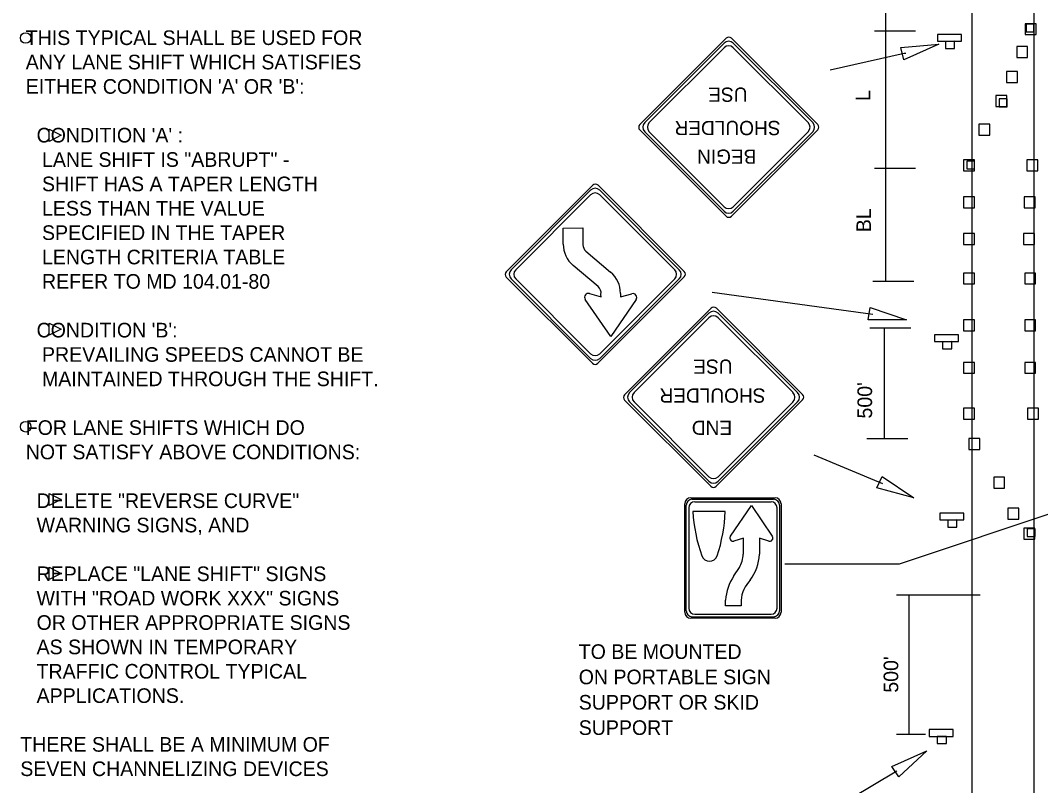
# Model space of a CAD drawing. Extents: x 1531.38 to 1538.58, y 1529.59 to 1539.28.
# Drawn here: x 1531.395 to 1535.582, y 1533.489 to 1536.629 of the extents above; entities that cross this region are included whole.
import ezdxf

# ---------------------------------------------------------------- set-up
doc = ezdxf.new("R2010")
doc.units = 0
for name, color, linetype in [('DETL-DIMS', 7, 'Continuous'), ('DETL-LINE', 7, 'Continuous'), ('DETL-NOTE', 7, 'Continuous'), ('USER-BORD', 7, 'Continuous')]:
    doc.layers.add(name, color=color, linetype=linetype)

# ---------------------------------------------------------------- blocks, each defined once
blk = doc.blocks.new('CD20')
at = {"layer": 'USER-BORD'}
blk.add_lwpolyline([(-0.0625, -0.0625), (0, -0.0625), (0, 0), (-0.0625, 0)], close=True, dxfattribs=at)
blk = doc.blocks.new('SIGN13')
at = {"layer": 'USER-BORD'}
for points in [[(-0.0134, 0.0182), (0.011, 0.0189), (0.011, 0.0371), (-0.0134, 0.0371)], [(-0.0314, 0.0182), (-0.0314, 0), (0.032, 0), (0.032, 0.0182)]]:
    blk.add_lwpolyline(points, close=True, dxfattribs=at)

msp = doc.modelspace()

# ---------------------------------------------------------------- linework, layer by layer
at = {"layer": 'DETL-DIMS'}
for p, q in [((1534.9463, 1538.5537), (1534.9463, 1535.5589)), ((1534.901, 1536.5864), (1535.0689, 1536.5864)), ((1535.0219, 1536.4925), (1534.719, 1536.4242)), ((1535.0299, 1536.4925), (1535.0219, 1536.4925)), ((1534.901, 1536.0219), (1535.0689, 1536.0219)), ((1534.8937, 1535.5589), (1535.0617, 1535.5589)), ((1534.8937, 1535.4219), (1534.2339, 1535.512)), ((1534.8818, 1535.3674), (1535.0497, 1535.3674)), ((1534.9408, 1535.3674), (1534.9408, 1534.9127)), ((1534.8698, 1534.9127), (1535.0377, 1534.9127)), ((1534.9353, 1534.7269), (1534.6525, 1534.8449)), ((1535.6998, 1534.63), (1535.0012, 1534.3974)), ((1535.0012, 1534.3974), (1534.5326, 1534.3973)), ((1535.3342, 1534.2704), (1534.9914, 1534.2702)), ((1535.0412, 1534.2702), (1535.0412, 1533.6978)), ((1535.1099, 1533.6978), (1534.9914, 1533.6978)), ((1534.9925, 1533.5485), (1534.8025, 1533.4337))]:
    msp.add_line(p, q, dxfattribs=at)
for points in [[(1535.0215, 1536.4671), (1535.0084, 1536.517), (1535.1649, 1536.5316)], [(1534.8743, 1535.3994), (1534.8827, 1535.4504), (1535.0315, 1535.3996)], [(1534.9107, 1534.7101), (1534.9319, 1534.7572), (1535.0627, 1534.6701)], [(1535.0002, 1533.5243), (1534.9719, 1533.5676), (1535.1158, 1533.6309)]]:
    msp.add_lwpolyline(points, close=True, dxfattribs=at)
at = {"layer": 'DETL-LINE'}
for p, q in [((1535.3002, 1538.9346), (1535.3002, 1531.7918)), ((1535.5552, 1538.9346), (1535.5552, 1531.7918)), ((1534.2919, 1536.5559), (1533.9372, 1536.2011)), ((1534.6678, 1536.2019), (1534.3139, 1536.5559)), ((1533.9572, 1536.2094), (1534.2833, 1536.5356)), ((1534.2833, 1536.5168), (1533.976, 1536.2094)), ((1534.321, 1536.5356), (1534.6471, 1536.2094)), ((1534.6283, 1536.2094), (1534.321, 1536.5168)), ((1531.5127, 1536.1322), (1531.5127, 1536.1822)), ((1531.5127, 1536.1822), (1531.5627, 1536.1572)), ((1533.9372, 1536.1792), (1534.2912, 1535.8253)), ((1534.2833, 1535.8456), (1533.9572, 1536.1718)), ((1533.976, 1536.1718), (1534.2833, 1535.8644)), ((1534.3131, 1535.8253), (1534.6678, 1536.1799)), ((1534.6471, 1536.1718), (1534.321, 1535.8456)), ((1534.321, 1535.8644), (1534.6283, 1536.1718)), ((1534.6283, 1536.2094), (1534.6283, 1536.2094)), ((1531.5627, 1536.1572), (1531.5127, 1536.1322)), ((1533.744, 1535.9522), (1533.3893, 1535.5975)), ((1533.4092, 1535.6058), (1533.7354, 1535.932)), ((1534.1199, 1535.5983), (1533.7659, 1535.9522)), ((1533.7731, 1535.932), (1534.0992, 1535.6058)), ((1533.7354, 1535.9132), (1533.4281, 1535.6058)), ((1534.0804, 1535.6058), (1533.773, 1535.9132)), ((1533.623, 1535.7767), (1533.7036, 1535.7769)), ((1533.6231, 1535.7105), (1533.623, 1535.7767)), ((1533.7036, 1535.7769), (1533.7037, 1535.7082)), ((1533.7158, 1535.6821), (1533.8176, 1535.5959)), ((1533.766, 1535.5367), (1533.6636, 1535.6234)), ((1534.0804, 1535.6058), (1534.0804, 1535.6058)), ((1533.3893, 1535.5755), (1533.7433, 1535.2216)), ((1533.7354, 1535.242), (1533.4092, 1535.5681)), ((1533.4281, 1535.5682), (1533.7354, 1535.2608)), ((1533.7652, 1535.2216), (1534.1199, 1535.5763)), ((1534.0992, 1535.5681), (1533.7731, 1535.242)), ((1533.7731, 1535.2608), (1534.0804, 1535.5681)), ((1533.7311, 1535.5081), (1533.778, 1535.4939)), ((1533.7781, 1535.4939), (1533.7776, 1535.5042)), ((1533.7776, 1535.5042), (1533.7776, 1535.5042)), ((1533.8581, 1535.5087), (1533.8581, 1535.4943)), ((1533.8581, 1535.4943), (1533.9046, 1535.5073)), ((1533.8189, 1535.3317), (1533.7135, 1535.4841)), ((1533.9219, 1535.4833), (1533.8189, 1535.3317)), ((1534.2297, 1535.4477), (1533.8749, 1535.0929)), ((1533.8949, 1535.1012), (1534.221, 1535.4274)), ((1534.6055, 1535.0937), (1534.2516, 1535.4477)), ((1534.2587, 1535.4274), (1534.5849, 1535.1012)), ((1531.5127, 1535.337), (1531.5127, 1535.387)), ((1531.5127, 1535.387), (1531.5627, 1535.362)), ((1534.221, 1535.4086), (1533.9137, 1535.1012)), ((1534.5661, 1535.1012), (1534.2587, 1535.4086)), ((1531.5627, 1535.362), (1531.5127, 1535.337)), ((1534.5661, 1535.1012), (1534.5661, 1535.1012)), ((1533.8749, 1535.071), (1534.2289, 1534.7171)), ((1534.221, 1534.7374), (1533.8949, 1535.0636)), ((1533.9137, 1535.0636), (1534.221, 1534.7562)), ((1534.2509, 1534.7171), (1534.6055, 1535.0717)), ((1534.5849, 1535.0636), (1534.2587, 1534.7374)), ((1534.2587, 1534.7562), (1534.5661, 1535.0636)), ((1531.5127, 1534.6377), (1531.5127, 1534.6877)), ((1531.5127, 1534.6877), (1531.5627, 1534.6627)), ((1531.5627, 1534.6627), (1531.5127, 1534.6377)), ((1534.1463, 1534.67), (1534.4924, 1534.67)), ((1534.1524, 1534.6639), (1534.4861, 1534.6639)), ((1534.1216, 1534.2003), (1534.1216, 1534.6453)), ((1534.1277, 1534.2064), (1534.1277, 1534.6391)), ((1534.1381, 1534.6288), (1534.1381, 1534.2168)), ((1534.1628, 1534.6535), (1534.4759, 1534.6535)), ((1534.3091, 1534.5116), (1534.3952, 1534.638)), ((1534.3952, 1534.638), (1534.4812, 1534.5116)), ((1534.5006, 1534.2168), (1534.5006, 1534.6288)), ((1534.5109, 1534.6391), (1534.5109, 1534.2064)), ((1534.5171, 1534.6453), (1534.5171, 1534.2003)), ((1534.1554, 1534.6143), (1534.2872, 1534.6143)), ((1534.3622, 1534.5045), (1534.3238, 1534.492)), ((1534.3622, 1534.4384), (1534.3622, 1534.5043)), ((1534.4663, 1534.492), (1534.4279, 1534.5045)), ((1534.4281, 1534.5043), (1534.4281, 1534.4384)), ((1531.5127, 1534.3345), (1531.5127, 1534.3845)), ((1531.5127, 1534.3845), (1531.5627, 1534.3595)), ((1534.3238, 1534.3491), (1534.3461, 1534.3837)), ((1531.5627, 1534.3595), (1531.5127, 1534.3345)), ((1534.2893, 1534.2268), (1534.2893, 1534.2492)), ((1534.3527, 1534.2492), (1534.3527, 1534.2268)), ((1534.3527, 1534.2268), (1534.2893, 1534.2268)), ((1534.4924, 1534.1756), (1534.1463, 1534.1756)), ((1534.1524, 1534.1817), (1534.4861, 1534.1817)), ((1534.1628, 1534.1921), (1534.4759, 1534.1921))]:
    msp.add_line(p, q, dxfattribs=at)
for points in [[(1535.5191, 1536.5705), (1535.5639, 1536.5705), (1535.5639, 1536.6153), (1535.5191, 1536.6153)], [(1535.4842, 1536.4767), (1535.529, 1536.4767), (1535.529, 1536.5215), (1535.4842, 1536.5215)], [(1535.4427, 1536.3742), (1535.4875, 1536.3742), (1535.4875, 1536.419), (1535.4427, 1536.419)], [(1535.3991, 1536.2761), (1535.4439, 1536.2761), (1535.4439, 1536.3209), (1535.3991, 1536.3209)], [(1535.3293, 1536.1583), (1535.3741, 1536.1583), (1535.3741, 1536.2031), (1535.3293, 1536.2031)], [(1535.2661, 1536.0121), (1535.3109, 1536.0121), (1535.3109, 1536.0569), (1535.2661, 1536.0569)], [(1535.5256, 1536.0121), (1535.5704, 1536.0121), (1535.5704, 1536.0569), (1535.5256, 1536.0569)], [(1535.2661, 1535.8595), (1535.3109, 1535.8595), (1535.3109, 1535.9043), (1535.2661, 1535.9043)], [(1535.5149, 1535.8595), (1535.5597, 1535.8595), (1535.5597, 1535.9043), (1535.5149, 1535.9043)], [(1535.2661, 1535.7092), (1535.3109, 1535.7092), (1535.3109, 1535.754), (1535.2661, 1535.754)], [(1535.5126, 1535.7092), (1535.5574, 1535.7092), (1535.5574, 1535.754), (1535.5126, 1535.754)], [(1535.2661, 1535.5471), (1535.3109, 1535.5471), (1535.3109, 1535.5919), (1535.2661, 1535.5919)], [(1535.5173, 1535.5471), (1535.5621, 1535.5471), (1535.5621, 1535.5919), (1535.5173, 1535.5919)], [(1535.2661, 1535.3546), (1535.3109, 1535.3546), (1535.3109, 1535.3994), (1535.2661, 1535.3994)], [(1535.5173, 1535.3546), (1535.5621, 1535.3546), (1535.5621, 1535.3994), (1535.5173, 1535.3994)], [(1535.2661, 1535.1808), (1535.3109, 1535.1808), (1535.3109, 1535.2256), (1535.2661, 1535.2256)], [(1535.5173, 1535.1808), (1535.5621, 1535.1808), (1535.5621, 1535.2256), (1535.5173, 1535.2256)], [(1535.2661, 1534.9929), (1535.3109, 1534.9929), (1535.3109, 1535.0377), (1535.2661, 1535.0377)], [(1535.529, 1534.9929), (1535.5738, 1534.9929), (1535.5738, 1535.0377), (1535.529, 1535.0377)], [(1535.2881, 1534.8678), (1535.3329, 1534.8678), (1535.3329, 1534.9126), (1535.2881, 1534.9126)], [(1535.3898, 1534.7097), (1535.4346, 1534.7097), (1535.4346, 1534.7545), (1535.3898, 1534.7545)], [(1535.4484, 1534.5819), (1535.4932, 1534.5819), (1535.4932, 1534.6267), (1535.4484, 1534.6267)], [(1535.5141, 1534.4997), (1535.5589, 1534.4997), (1535.5589, 1534.5445), (1535.5141, 1534.5445)]]:
    msp.add_lwpolyline(points, close=True, dxfattribs=at)
for centre in [(1531.4164, 1536.5567), (1531.4164, 1534.9614)]:
    msp.add_circle(centre, 0.0217, dxfattribs=at)
for centre, radius, start, end in [((1534.3029, 1536.5449), 0.0155, 45, 135), ((1534.3022, 1536.5168), 0.0266, 45, 135), ((1534.3021, 1536.498), 0.0266, 45, 135), ((1533.9482, 1536.1901), 0.0155, 135, 225), ((1533.976, 1536.1906), 0.0266, 135, 225), ((1533.9948, 1536.1906), 0.0266, 135, 225), ((1534.6095, 1536.1906), 0.0266, 315, 45), ((1534.6284, 1536.1906), 0.0266, 315, 45), ((1534.6569, 1536.1909), 0.0155, 315, 45), ((1533.7542, 1535.9131), 0.0266, 45, 135), ((1533.7542, 1535.8943), 0.0266, 45, 135), ((1533.755, 1535.9412), 0.0155, 45, 135), ((1534.3022, 1535.8832), 0.0266, 225, 315), ((1534.3022, 1535.8644), 0.0266, 225, 315), ((1534.3021, 1535.8362), 0.0155, 225, 315), ((1533.7375, 1535.7107), 0.1144, 180.094, 229.7591), ((1533.738, 1535.7082), 0.0343, 180.094, 229.7591), ((1533.4003, 1535.5865), 0.0155, 135, 225), ((1533.428, 1535.587), 0.0266, 135, 225), ((1533.4468, 1535.587), 0.0266, 135, 225), ((1533.7436, 1535.5085), 0.1144, 0.094, 49.7591), ((1534.0616, 1535.5869), 0.0266, 315, 45), ((1534.0804, 1535.5869), 0.0266, 315, 45), ((1534.1089, 1535.5873), 0.0155, 315, 45), ((1533.7265, 1535.4929), 0.0157, 73.1964, 214.3543), ((1533.7438, 1535.5105), 0.0343, 349.3489, 49.7591), ((1533.9088, 1535.4921), 0.0157, 325.8336, 105.5836), ((1534.2398, 1535.3898), 0.0266, 45, 135), ((1534.2399, 1535.4086), 0.0266, 45, 135), ((1534.2407, 1535.4367), 0.0155, 45, 135), ((1533.7542, 1535.2796), 0.0266, 225, 315), ((1533.7542, 1535.2608), 0.0266, 225, 315), ((1533.7542, 1535.2326), 0.0155, 225, 315), ((1533.8859, 1535.0819), 0.0155, 135, 225), ((1533.9137, 1535.0824), 0.0266, 135, 225), ((1533.9325, 1535.0824), 0.0266, 135, 225), ((1534.5472, 1535.0824), 0.0266, 315, 45), ((1534.5661, 1535.0824), 0.0266, 315, 45), ((1534.5946, 1535.0827), 0.0155, 315, 45), ((1534.2399, 1534.775), 0.0266, 225, 315), ((1534.2399, 1534.7562), 0.0266, 225, 315), ((1534.2399, 1534.728), 0.0155, 225, 315), ((1534.1463, 1534.6452), 0.0247, 90, 180), ((1534.1524, 1534.6391), 0.0247, 90, 180), ((1534.4861, 1534.6391), 0.0247, 0, 90), ((1534.4923, 1534.6452), 0.0247, 0, 90), ((1534.1627, 1534.6287), 0.0247, 90, 180), ((1534.4759, 1534.6287), 0.0247, 0, 90), ((1534.7575, 1534.641), 0.6028, 182.5529, 200.3658), ((1533.6835, 1534.6285), 0.6039, 340.9328, 358.6381), ((1534.3198, 1534.5043), 0.0129, 145.7397, 288), ((1534.4704, 1534.5043), 0.0129, 252, 34.2603), ((1534.2234, 1534.4427), 0.033, 200.3641, 339.6359), ((1534.2305, 1534.4472), 0.1319, 331.1838, 356.1678), ((1534.2305, 1534.4472), 0.1977, 324.1907, 357.4446), ((1534.4851, 1534.2378), 0.196, 145.3872, 176.6343), ((1534.4851, 1534.2378), 0.1329, 135.1307, 175.032), ((1534.1524, 1534.2064), 0.0247, 180, 270), ((1534.1627, 1534.2168), 0.0247, 180, 270), ((1534.4759, 1534.2168), 0.0247, 270, 360), ((1534.4861, 1534.2064), 0.0247, 270, 360), ((1534.1463, 1534.2003), 0.0247, 180, 270), ((1534.4923, 1534.2003), 0.0247, 270, 360)]:
    msp.add_arc(centre, radius, start, end, dxfattribs=at)

# ---------------------------------------------------------------- block references
at = {"layer": 'DETL-LINE', "xscale": 0.5153677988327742, "yscale": 0.5153677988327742}
for p in [(1535.5549, 1536.6136), (1535.4446, 1536.3065), (1535.3112, 1536.0515), (1535.5596, 1534.5426)]:
    msp.add_blockref('CD20', p, dxfattribs=at)
at = {"layer": 'DETL-LINE', "xscale": 1.550372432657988, "yscale": 1.550372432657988, "rotation": 180}
for p in [(1535.2087, 1536.5716), (1535.1968, 1535.339), (1535.2184, 1534.6073), (1535.1752, 1533.719)]:
    msp.add_blockref('SIGN13', p, dxfattribs=at)

# ---------------------------------------------------------------- texts
at = {"layer": 'DETL-LINE'}
for s, p in [('USE', (1534.3793, 1536.3533)), ('SHOULDER', (1534.5147, 1536.2165)), ('BEGIN', (1534.4158, 1536.0988)), ('USE', (1534.3176, 1535.2371)), ('SHOULDER', (1534.453, 1535.1185)), ('END', (1534.316, 1534.9863))]:
    msp.add_text(s, height=0.05854, rotation=180, dxfattribs=at).set_placement(p)
at = {"layer": 'DETL-NOTE'}
for s, p in [(' THIS TYPICAL SHALL BE USED FOR ', (1531.3942, 1536.5278)), (' ANY LANE SHIFT WHICH SATISFIES ', (1531.3942, 1536.4278)), (" EITHER CONDITION 'A' OR 'B':", (1531.3942, 1536.3278)), ("   CONDITION 'A' :", (1531.3942, 1536.1278)), ('    LANE SHIFT IS "ABRUPT" -', (1531.3942, 1536.0278)), ('    SHIFT HAS A TAPER LENGTH ', (1531.3942, 1535.9278)), ('    LESS THAN THE VALUE ', (1531.3942, 1535.8278)), ('    SPECIFIED IN THE TAPER ', (1531.3942, 1535.7278)), ('    LENGTH CRITERIA TABLE', (1531.3942, 1535.6278)), ('    REFER TO MD 104.01-80', (1531.3942, 1535.5278)), ("   CONDITION 'B':", (1531.3942, 1535.3278)), ('    PREVAILING SPEEDS CANNOT BE ', (1531.3942, 1535.2278)), ('    MAINTAINED THROUGH THE SHIFT.', (1531.3942, 1535.1278)), (' FOR LANE SHIFTS WHICH DO ', (1531.3942, 1534.9278)), (' NOT SATISFY ABOVE CONDITIONS:', (1531.3942, 1534.8278)), ('   DELETE "REVERSE CURVE"', (1531.3942, 1534.6278)), ('   WARNING SIGNS, AND', (1531.3942, 1534.5278)), ('   REPLACE "LANE SHIFT" SIGNS', (1531.3942, 1534.3278)), ('   WITH "ROAD WORK XXX" SIGNS ', (1531.3942, 1534.2278)), ('   OR OTHER APPROPRIATE SIGNS ', (1531.3942, 1534.1278)), ('   AS SHOWN IN TEMPORARY', (1531.3942, 1534.0278)), ('TO BE MOUNTED', (1533.6865, 1534.0085)), ('   TRAFFIC CONTROL TYPICAL', (1531.3942, 1533.9278)), ('ON PORTABLE SIGN', (1533.6865, 1533.9045)), ('   APPLICATIONS.', (1531.3942, 1533.8278)), ('SUPPORT OR SKID', (1533.6865, 1533.8005)), ('SUPPORT', (1533.6865, 1533.6965)), ('THERE SHALL BE A MINIMUM OF ', (1531.3942, 1533.6278)), ('SEVEN CHANNELIZING DEVICES ', (1531.3942, 1533.5278))]:
    msp.add_text(s, height=0.06, dxfattribs=at).set_placement(p)
for s, p in [('L', (1534.8838, 1536.2981)), ('BL', (1534.8862, 1535.7597)), ("500'", (1534.8906, 1534.995)), ("500'", (1534.9981, 1533.8699))]:
    msp.add_text(s, height=0.06, rotation=90, dxfattribs=at).set_placement(p)

doc.saveas('drawing.dxf')
